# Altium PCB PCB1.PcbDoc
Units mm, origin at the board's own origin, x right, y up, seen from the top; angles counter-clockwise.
Board outline 79.4 x 57.96 mm, 2 copper layers (Top Layer, Bottom Layer); 3 components, 28 nets, 56 pads, 17 vias.
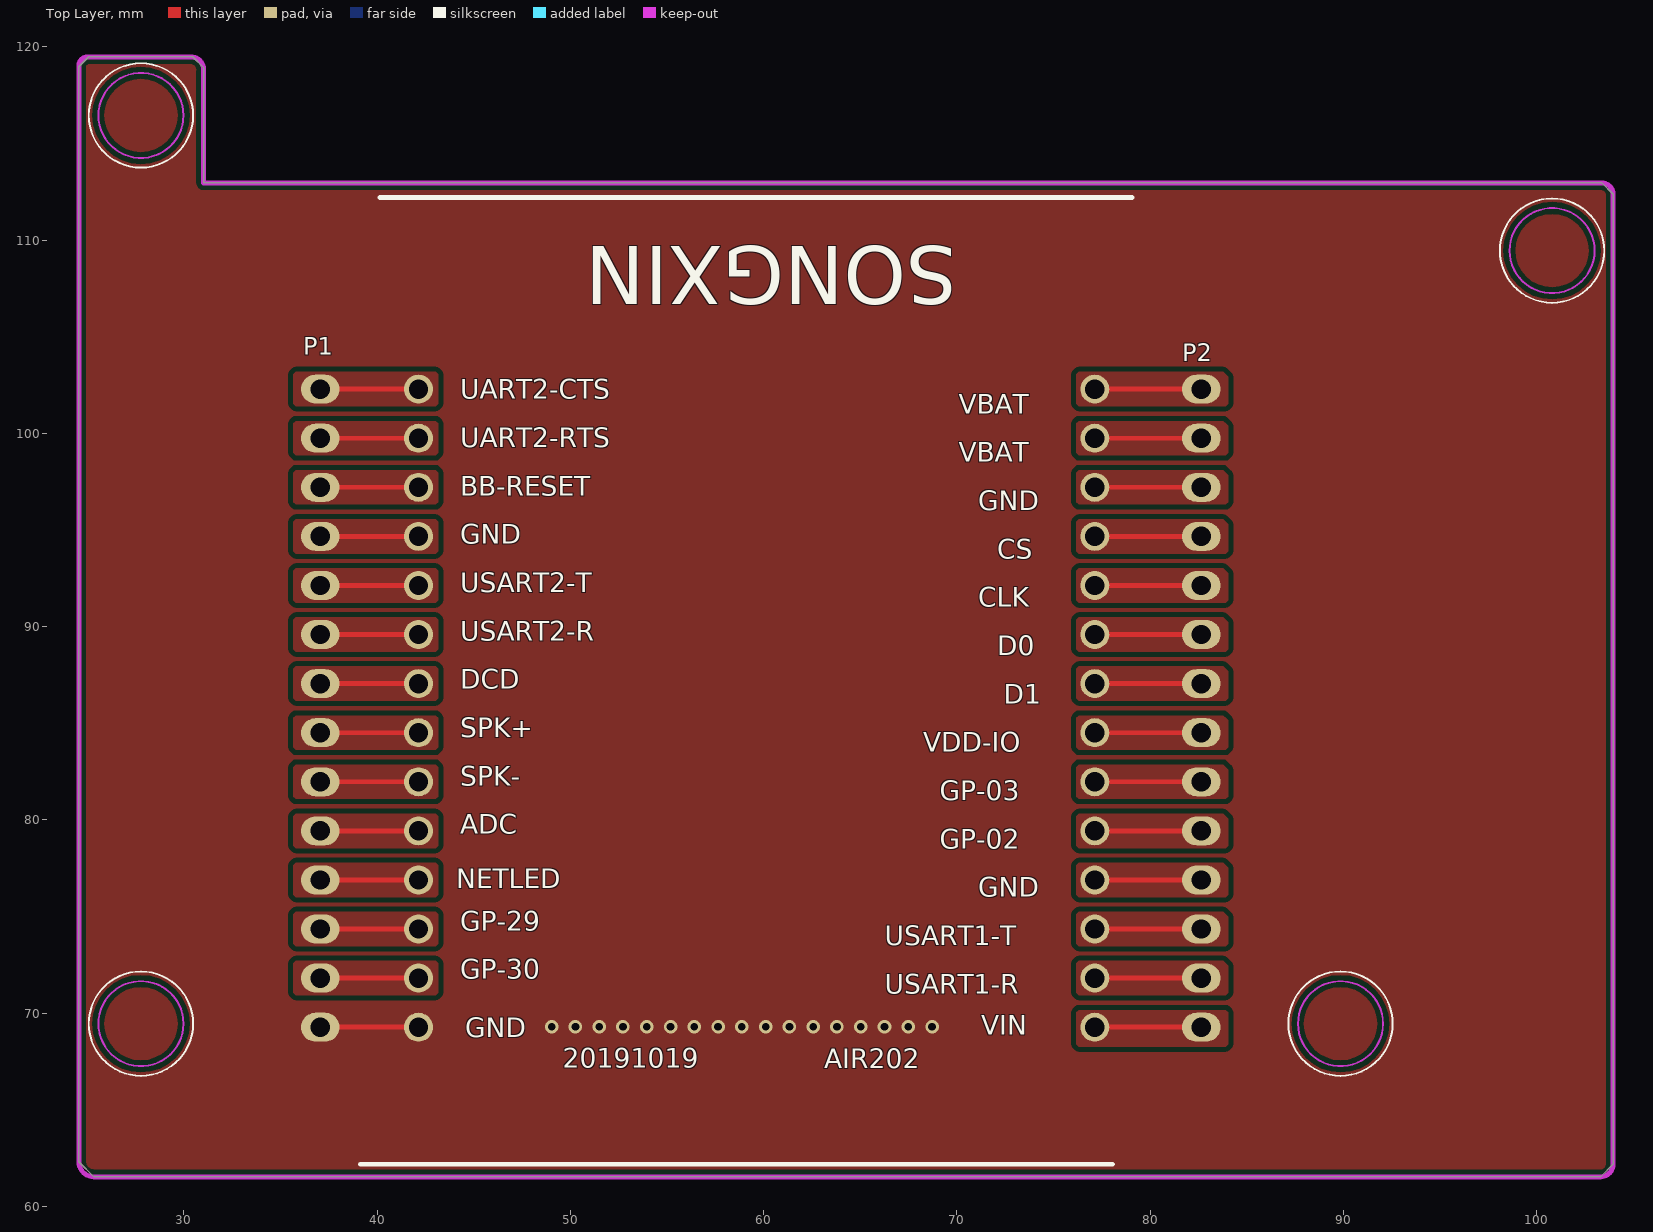
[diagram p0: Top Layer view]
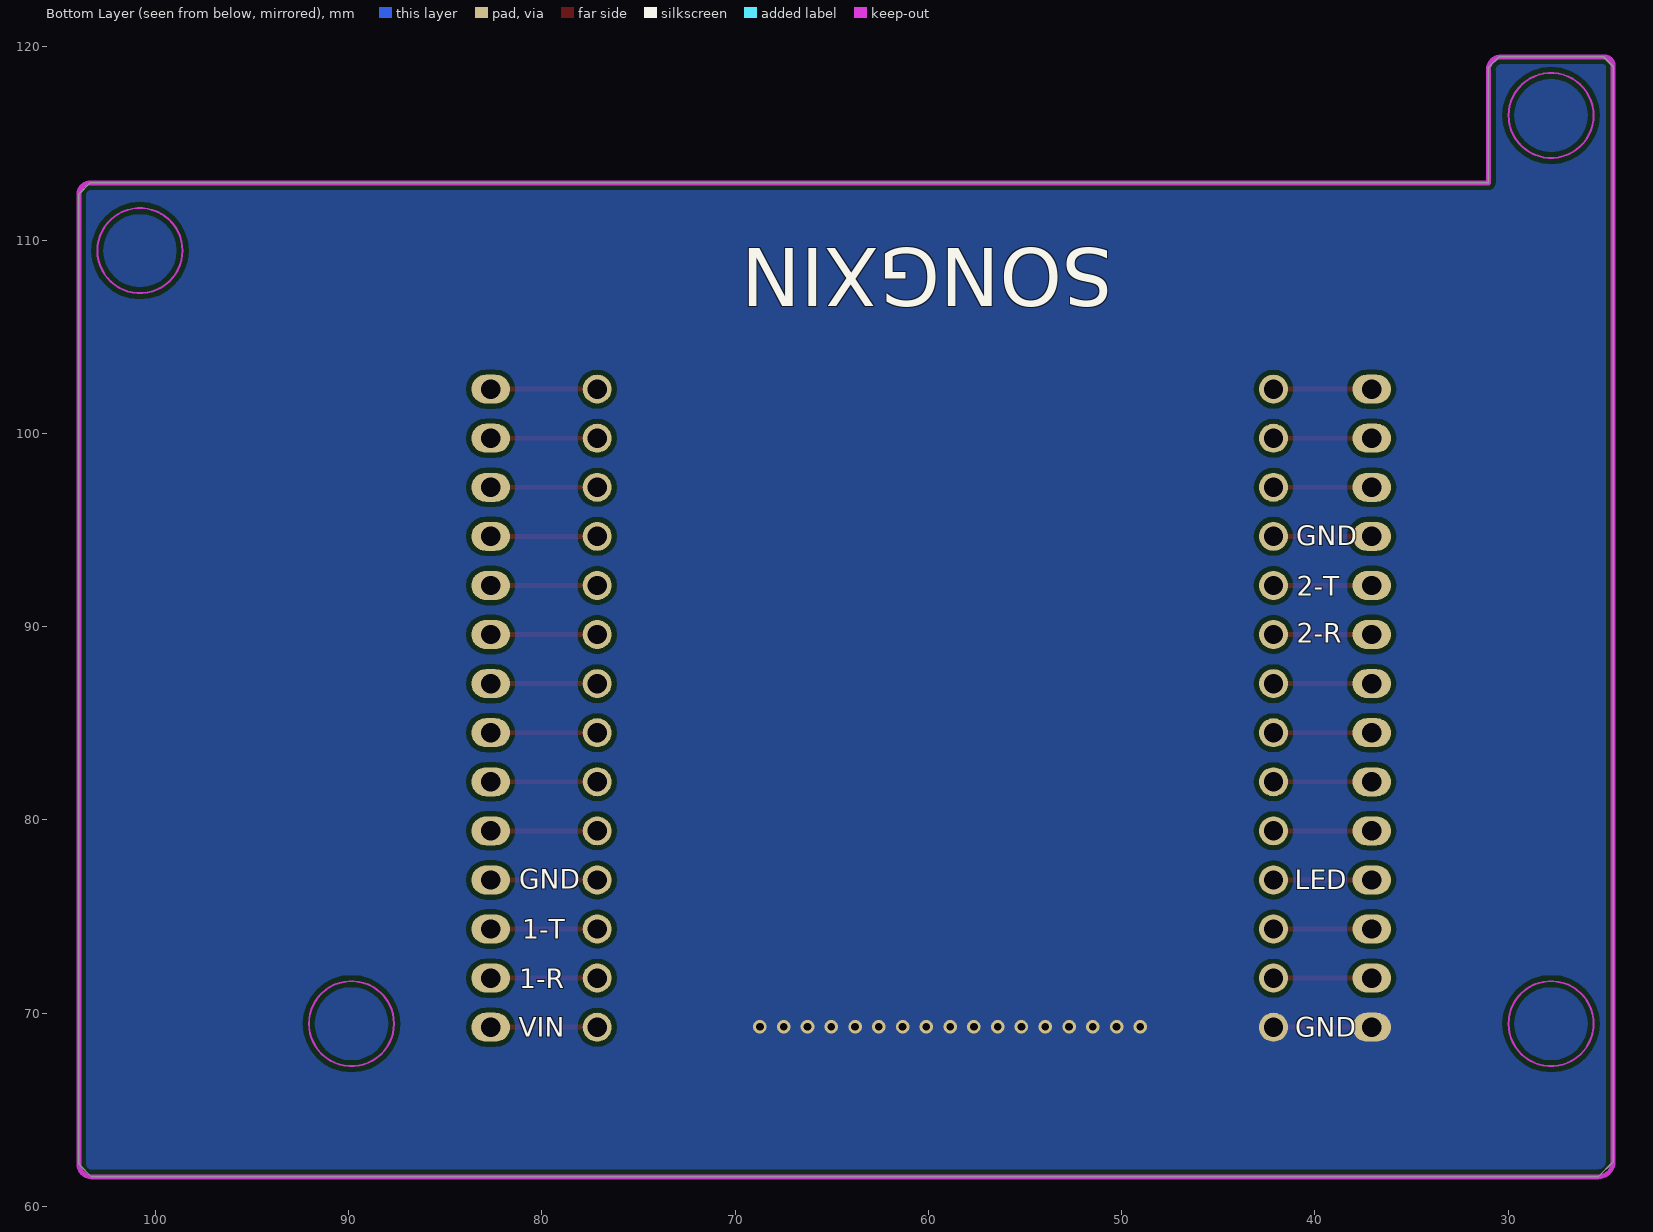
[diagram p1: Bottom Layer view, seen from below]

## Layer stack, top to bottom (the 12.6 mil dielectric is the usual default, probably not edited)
Top Layer: signal copper 0.0356
Dielectric: dielectric 0.32, FR-4, Dk 4.8
Bottom Layer: signal copper 0.0356

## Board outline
25.07,119.482 30.455,119.482 31.013,118.923 31.013,118.72 31.013,112.954 103.378,112.954 103.962,112.37 103.962,62.179 103.302,61.519 25.349,61.519 24.562,62.306 24.562,118.974 25.07,119.482

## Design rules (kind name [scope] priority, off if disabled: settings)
Clearance [All] p1: gap=0.254
ComponentClearance [All] p1: gap=0.254 collisioncheckmode=3 verticalgap=0.254
PolygonConnect [All] p1: connectstyle=Direct reliefconductorwidth=0.254 reliefentries=4 polygonreliefangle="90 Angle"
RoutingVias [All] p1: holewidth=0.711 width=1.27 viastyle="Through Hole" minholewidth=0.711 minwidth=1.27 maxholewidth=0.711 maxwidth=1.27
SolderMaskExpansion [All] p1: expansion=0.102
TestPointUsage FabricationTestPointUsage [All] p1: valid=0 allowmultiple=FALSE
Testpoint FabricationTestpoint [(IsPad And (OnTopLayer Or OnBottomLayer))] p1: side=3 testpointundercomponent=TRUE minsize=1.016 maxsize=2.54 preferedsize=1.524 minholesize=0 maxholesize=1.016 preferedholesize=0.813 testpointgrid=0.025 style=297 order=0123456789
Width [All] p1: maxlimit=0.254 minlimit=0.254 preferedwidth=0.254
18 further rules are at their usual default settings.

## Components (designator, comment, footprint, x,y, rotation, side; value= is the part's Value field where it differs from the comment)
AIR202 "AIR202" AIR202 42.139,87.046 r0 top
P1 "P1" P1 37.059,69.266 r0 top
P2 "P2" P2 82.652,69.266 r0 top

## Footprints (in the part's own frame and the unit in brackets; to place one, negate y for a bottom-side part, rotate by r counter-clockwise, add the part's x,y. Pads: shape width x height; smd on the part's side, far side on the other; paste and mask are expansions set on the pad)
AIR202 [mm]
  round 1.5 hole 1 unplated: 1(0,15.24) 2(0,12.7) 3(0,10.16) 4(0,7.62) 5(0,5.08) 6(0,2.54) 7(0,0) 8(0,-2.54) 9(0,-5.08) 10(0,-7.62) 11(0,-10.16) 12(0,-12.7) 13(0,-15.24) 14(0,-17.78) 15(35,-17.78) 16(35,-15.24) 17(35,-12.7) 18(35,-10.16) 19(35,-7.62) 20(35,-5.08) 21(35,-2.54) 22(35,0) 23(35,2.54) 24(35,5.08) 25(35,7.62) 26(35,10.16) 27(35,12.7) 28(35,15.24)
P1 [mm]
  oval 2x1.5 hole 1 unplated: 1(0,33.02) 2(0,30.48) 3(0,27.94) 4(0,25.4) 5(0,22.86) 6(0,20.32) 7(0,17.78) 8(0,15.24) 9(0,12.7) 10(0,10.16) 11(0,7.62) 12(0,5.08) 13(0,2.54) 14(0,0)
P2 [mm]
  oval 2x1.5 hole 1 unplated: 15(0,0) 16(0,2.54) 17(0,5.08) 18(0,7.62) 19(0,10.16) 20(0,12.7) 21(0,15.24) 22(0,17.78) 23(0,20.32) 24(0,22.86) 25(0,25.4) 26(0,27.94) 27(0,30.48) 28(0,33.02)

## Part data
AIR202: library part Component_1

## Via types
v1: diameter 0.7, hole 0.4, Top Layer to Bottom Layer, 17 vias

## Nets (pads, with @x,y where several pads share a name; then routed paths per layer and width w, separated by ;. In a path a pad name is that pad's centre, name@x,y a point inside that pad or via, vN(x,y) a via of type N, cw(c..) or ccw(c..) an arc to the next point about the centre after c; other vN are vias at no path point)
GND: AIR202.14 P1.14 | length 5.1
  Top Layer w0.254: P1.14 AIR202.14
  other v1: 49.03,69.291 50.26,69.291 51.491,69.291 52.721,69.291 53.951,69.291 55.181,69.291 56.412,69.291 57.642,69.291 58.872,69.291 60.103,69.291 61.333,69.291 62.563,69.291 63.794,69.291 65.024,69.291 66.254,69.291 67.485,69.291 68.715,69.291
NetAIR202_1: AIR202.1 P1.1 | length 5.1
  Top Layer w0.254: P1.1 AIR202.1
NetAIR202_2: AIR202.2 P1.2 | length 5.1
  Top Layer w0.254: P1.2 AIR202.2
NetAIR202_3: AIR202.3 P1.3 | length 5.1
  Top Layer w0.254: P1.3 AIR202.3
NetAIR202_4: AIR202.4 P1.4 | length 5.1
  Top Layer w0.254: P1.4 AIR202.4
NetAIR202_5: AIR202.5 P1.5 | length 5.1
  Top Layer w0.254: P1.5 AIR202.5
NetAIR202_6: AIR202.6 P1.6 | length 5.1
  Top Layer w0.254: P1.6 AIR202.6
NetAIR202_7: AIR202.7 P1.7 | length 5.1
  Top Layer w0.254: P1.7 AIR202.7
NetAIR202_8: AIR202.8 P1.8 | length 5.1
  Top Layer w0.254: P1.8 AIR202.8
NetAIR202_9: AIR202.9 P1.9 | length 5.1
  Top Layer w0.254: P1.9 AIR202.9
NetAIR202_10: AIR202.10 P1.10 | length 5.1
  Top Layer w0.254: P1.10 AIR202.10
NetAIR202_11: AIR202.11 P1.11 | length 5.1
  Top Layer w0.254: P1.11 AIR202.11
NetAIR202_12: AIR202.12 P1.12 | length 5.1
  Top Layer w0.254: P1.12 AIR202.12
NetAIR202_13: AIR202.13 P1.13 | length 5.1
  Top Layer w0.254: P1.13 AIR202.13
NetAIR202_16: AIR202.16 P2.16 | length 5.5
  Top Layer w0.254: AIR202.16 P2.16
NetAIR202_17: AIR202.17 P2.17 | length 5.5
  Top Layer w0.254: AIR202.17 P2.17
NetAIR202_18: AIR202.18 P2.18 | length 5.5
  Top Layer w0.254: AIR202.18 P2.18
NetAIR202_19: AIR202.19 P2.19 | length 5.5
  Top Layer w0.254: AIR202.19 P2.19
NetAIR202_20: AIR202.20 P2.20 | length 5.5
  Top Layer w0.254: AIR202.20 P2.20
NetAIR202_21: AIR202.21 P2.21 | length 5.5
  Top Layer w0.254: AIR202.21 P2.21
NetAIR202_22: AIR202.22 P2.22 | length 5.5
  Top Layer w0.254: AIR202.22 P2.22
NetAIR202_23: AIR202.23 P2.23 | length 5.5
  Top Layer w0.254: AIR202.23 P2.23
NetAIR202_24: AIR202.24 P2.24 | length 5.5
  Top Layer w0.254: AIR202.24 P2.24
NetAIR202_25: AIR202.25 P2.25 | length 5.5
  Top Layer w0.254: AIR202.25 P2.25
NetAIR202_26: AIR202.26 P2.26 | length 5.5
  Top Layer w0.254: AIR202.26 P2.26
NetAIR202_27: AIR202.27 P2.27 | length 5.5
  Top Layer w0.254: AIR202.27 P2.27
NetAIR202_28: AIR202.28 P2.28 | length 5.5
  Top Layer w0.254: AIR202.28 P2.28
VCC: AIR202.15 P2.15 | length 5.5
  Top Layer w0.254: AIR202.15 P2.15

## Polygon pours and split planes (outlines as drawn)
VCC on Top Layer "Top Layer-No Net 2" (solid, pour order 1000): 76.302,70.155 83.922,70.155 84.049,70.028 84.049,68.377 83.922,68.25 76.302,68.25 76.175,68.377 76.175,70.028 76.302,70.155
NetAIR202_16 on Top Layer "Top Layer-No Net 2" (solid, pour order 1001): 76.302,72.695 83.795,72.695 83.922,72.568 84.049,72.441 84.049,71.171 84.049,71.044 83.922,70.917 76.302,70.917 76.175,71.044 76.175,72.568 76.302,72.695
NetAIR202_17 on Top Layer "Top Layer-No Net 2" (solid, pour order 1002): 76.302,75.235 83.795,75.235 83.922,75.108 84.049,74.981 84.049,73.711 84.049,73.584 83.922,73.457 76.302,73.457 76.175,73.584 76.175,75.108 76.302,75.235
NetAIR202_18 on Top Layer "Top Layer-No Net 2" (solid, pour order 1003): 76.302,77.775 83.795,77.775 83.922,77.648 84.049,77.521 84.049,76.251 84.049,76.124 83.922,75.997 76.302,75.997 76.175,76.124 76.175,77.648 76.302,77.775
NetAIR202_19 on Top Layer "Top Layer-No Net 2" (solid, remove dead copper, pour order 1004): 76.302,80.315 83.795,80.315 83.922,80.188 84.049,80.061 84.049,78.791 84.049,78.664 83.922,78.537 76.302,78.537 76.175,78.664 76.175,80.188 76.302,80.315
NetAIR202_20 on Top Layer "Top Layer-No Net 2" (solid, remove dead copper, pour order 1005): 76.302,82.855 83.795,82.855 83.922,82.728 84.049,82.601 84.049,81.331 84.049,81.204 83.922,81.077 76.302,81.077 76.175,81.204 76.175,82.728 76.302,82.855
NetAIR202_21 on Top Layer "Top Layer-No Net 2" (solid, remove dead copper, pour order 1006): 76.302,85.395 83.795,85.395 83.922,85.268 84.049,85.141 84.049,83.871 84.049,83.744 83.922,83.617 76.302,83.617 76.175,83.744 76.175,85.268 76.302,85.395
NetAIR202_22 on Top Layer "Top Layer-No Net 2" (solid, remove dead copper, pour order 1007): 76.302,87.935 83.795,87.935 83.922,87.808 84.049,87.681 84.049,86.411 84.049,86.284 83.922,86.157 76.302,86.157 76.175,86.284 76.175,87.808 76.302,87.935
NetAIR202_23 on Top Layer "Top Layer-No Net 2" (solid, remove dead copper, pour order 1008): 76.302,90.475 83.795,90.475 83.922,90.348 84.049,90.221 84.049,88.951 84.049,88.824 83.922,88.697 76.302,88.697 76.175,88.824 76.175,90.348 76.302,90.475
NetAIR202_24 on Top Layer "Top Layer-No Net 2" (solid, remove dead copper, pour order 1009): 76.302,93.015 83.795,93.015 83.922,92.888 84.049,92.761 84.049,91.491 84.049,91.364 83.922,91.237 76.302,91.237 76.175,91.364 76.175,92.888 76.302,93.015
NetAIR202_25 on Top Layer "Top Layer-No Net 2" (solid, remove dead copper, pour order 1010): 76.302,95.555 83.795,95.555 83.922,95.428 84.049,95.301 84.049,94.031 84.049,93.904 83.922,93.777 76.302,93.777 76.175,93.904 76.175,95.428 76.302,95.555
NetAIR202_26 on Top Layer "Top Layer-No Net 2" (solid, pour order 1011): 76.302,98.095 83.795,98.095 83.922,97.968 84.049,97.841 84.049,96.571 84.049,96.444 83.922,96.317 76.302,96.317 76.175,96.444 76.175,97.968 76.302,98.095
NetAIR202_27 on Top Layer "Top Layer-No Net 2" (solid, pour order 1012): 76.302,100.635 83.795,100.635 83.922,100.508 84.049,100.381 84.049,99.111 84.049,98.984 83.922,98.857 76.302,98.857 76.175,98.984 76.175,100.508 76.302,100.635
NetAIR202_28 on Top Layer "Top Layer-No Net 2" (solid, pour order 1013): 76.302,103.175 83.795,103.175 83.922,103.048 84.049,102.921 84.049,101.651 84.049,101.524 83.922,101.397 76.302,101.397 76.175,101.524 76.175,103.048 76.302,103.175
NetAIR202_11 on Top Layer "Top Layer-No Net 2" (solid, pour order 1014): 35.916,77.775 43.028,77.775 43.155,77.648 43.155,76.124 43.028,75.997 35.789,75.997 35.662,76.124 35.662,77.648 35.789,77.775 35.916,77.775
NetAIR202_12 on Top Layer "Top Layer-No Net 2" (solid, pour order 1015): 35.916,75.235 43.028,75.235 43.155,75.108 43.155,73.584 43.028,73.457 35.789,73.457 35.662,73.584 35.662,75.108 35.789,75.235 35.916,75.235
GND on Top Layer "Top Layer-No Net 2" (solid, pour order 1016): 35.916,70.155 43.028,70.155 43.155,70.028 43.155,68.504 43.028,68.377 35.789,68.377 35.662,68.504 35.662,70.028 35.789,70.155 35.916,70.155
NetAIR202_10 on Top Layer "Top Layer-No Net 2" (solid, remove dead copper, pour order 1017): 35.916,80.315 43.028,80.315 43.155,80.188 43.155,78.664 43.028,78.537 35.789,78.537 35.662,78.664 35.662,80.188 35.789,80.315 35.916,80.315
NetAIR202_9 on Top Layer "Top Layer-No Net 2" (solid, remove dead copper, pour order 1018): 35.916,82.855 43.028,82.855 43.155,82.728 43.155,81.204 43.028,81.077 35.789,81.077 35.662,81.204 35.662,82.728 35.789,82.855 35.916,82.855
NetAIR202_8 on Top Layer "Top Layer-No Net 2" (solid, remove dead copper, pour order 1019): 35.916,85.395 43.028,85.395 43.155,85.268 43.155,83.744 43.028,83.617 35.789,83.617 35.662,83.744 35.662,85.268 35.789,85.395 35.916,85.395
NetAIR202_7 on Top Layer "Top Layer-No Net 2" (solid, remove dead copper, pour order 1020): 35.916,87.935 43.028,87.935 43.155,87.808 43.155,86.284 43.028,86.157 35.789,86.157 35.662,86.284 35.662,87.808 35.789,87.935 35.916,87.935
NetAIR202_6 on Top Layer "Top Layer-No Net 2" (solid, remove dead copper, pour order 1021): 35.916,90.475 43.028,90.475 43.155,90.348 43.155,88.824 43.028,88.697 35.789,88.697 35.662,88.824 35.662,90.348 35.789,90.475 35.916,90.475
NetAIR202_5 on Top Layer "Top Layer-No Net 2" (solid, remove dead copper, pour order 1022): 35.916,93.015 43.028,93.015 43.155,92.888 43.155,91.364 43.028,91.237 35.789,91.237 35.662,91.364 35.662,92.888 35.789,93.015 35.916,93.015
NetAIR202_4 on Top Layer "Top Layer-No Net 2" (solid, remove dead copper, pour order 1023): 35.916,95.555 43.028,95.555 43.155,95.428 43.155,93.904 43.028,93.777 35.789,93.777 35.662,93.904 35.662,95.428 35.789,95.555 35.916,95.555
NetAIR202_3 on Top Layer "Top Layer-No Net 2" (solid, remove dead copper, pour order 1024): 35.916,98.095 43.028,98.095 43.155,97.968 43.155,96.444 43.028,96.317 35.789,96.317 35.662,96.444 35.662,97.968 35.789,98.095 35.916,98.095
NetAIR202_2 on Top Layer "Top Layer-No Net 2" (solid, remove dead copper, pour order 1025): 35.916,100.635 43.028,100.635 43.155,100.508 43.155,98.984 43.028,98.857 35.789,98.857 35.662,98.984 35.662,100.508 35.789,100.635 35.916,100.635
NetAIR202_1 on Top Layer "Top Layer-No Net 2" (solid, remove dead copper, pour order 1026): 35.916,103.175 43.028,103.175 43.155,103.048 43.155,101.524 43.028,101.397 35.789,101.397 35.662,101.524 35.662,103.048 35.789,103.175 35.916,103.175
NetAIR202_13 on Top Layer "Top Layer-No Net 2" (solid, pour order 1028): 35.916,72.695 43.028,72.695 43.155,72.568 43.155,71.044 43.028,70.917 35.789,70.917 35.662,71.044 35.662,72.568 35.789,72.695 35.916,72.695
GND on Top Layer "Top Layer-No Net" (solid, pour order 1000): 24.562,118.821 25.07,119.329 25.07,119.482 30.378,119.482 30.937,118.923 30.937,113.03 31.013,112.954 103.378,112.954 103.962,112.37 103.962,62.179 103.302,61.519 25.349,61.519 24.562,62.306 24.562,118.847
GND on Bottom Layer "Top Layer-No Net" (solid, pour order 1001): 25.07,119.482 30.531,119.482 31.013,118.999 31.013,113.208 31.267,112.954 103.378,112.954 103.962,112.37 103.962,62.179 103.302,61.519 25.349,61.519 24.562,62.306 24.562,118.974 25.07,119.482

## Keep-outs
Keep-Out Layer:
  circle w0.1: c27.776,116.449 r2.2
  circle w0.1: c100.801,109.454 r2.2
  circle w0.1: c89.853,69.449 r2.2
  circle w0.1: c27.776,69.449 r2.2
  lines w0.254: 24.562,62.306 ccw(c25.349,62.306) 25.349,61.519 103.302,61.519 ccw(c103.302,62.179) 103.962,62.179 103.962,112.37 ccw(c103.378,112.37) 103.378,112.954 31.013,112.954 31.013,118.72 ccw(c30.353,118.821) 30.455,119.482 25.07,119.482 ccw(c25.032,119.012) 24.562,119.05 24.562,62.306

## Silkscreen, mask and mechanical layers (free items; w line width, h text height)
Top Overlay:
  circle w0.1: c27.776,116.449 r2.7
  circle w0.1: c100.801,109.454 r2.7
  circle w0.1: c89.853,69.449 r2.7
  circle w0.1: c27.776,69.449 r2.7
  lines w0.254: 39.123,62.173 78.061,62.173 ; 40.139,112.211 79.077,112.211
  text "SONGXIN" at 70.002,109.677 h3 r180
  text "UART2-CTS" at 44.298,101.778 h1
  text "VBAT" at 70.101,101.016 h1
  text "UART2-RTS" at 44.298,99.277 h1
  text "VBAT" at 70.101,98.515 h1
  text "BB-RESET" at 44.298,96.776 h1
  text "GND" at 71.1,96.014 h1
  text "GND" at 44.298,94.275 h1
  text "CS" at 72.1,93.513 h1
  text "USART2-T" at 44.298,91.774 h1
  text "CLK" at 71.1,91.012 h1
  text "USART2-R" at 44.298,89.273 h1
  text "D0" at 72.1,88.511 h1
  text "DCD" at 44.298,86.772 h1
  text "D1" at 72.433,86.01 h1
  text "SPK+" at 44.298,84.271 h1
  text "VDD-IO" at 68.268,83.509 h1
  text "SPK-" at 44.298,81.77 h1
  text "GP-03" at 69.101,81.008 h1
  text "ADC" at 44.298,79.269 h1
  text "GP-02" at 69.101,78.507 h1
  text "NETLED" at 44.094,76.454 h1
  text "GND" at 71.1,76.007 h1
  text "GP-29" at 44.298,74.268 h1
  text "USART1-T" at 66.269,73.506 h1
  text "GP-30" at 44.298,71.767 h1
  text "USART1-R" at 66.269,71.005 h1
  text "VIN" at 71.267,68.885 h1
  text "GND" at 44.552,68.758 h1
  text "20191019" at 49.606,67.158 h1
Bottom Overlay:
  text "SONGXIN" at 50.47,109.576 h3 r180
  text "GND" at 40.97,94.209 h1
  text "2-T" at 40.945,91.592 h1
  text "2-R" at 40.945,89.154 h1
  text "GND" at 81.178,76.429 h1
  text "LED" at 41.046,76.403 h1
  text "1-T" at 81.026,73.838 h1
  text "1-R" at 81.178,71.272 h1
  text "GND" at 41.021,68.783 h1
  text "VIN" at 81.204,68.783 h1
